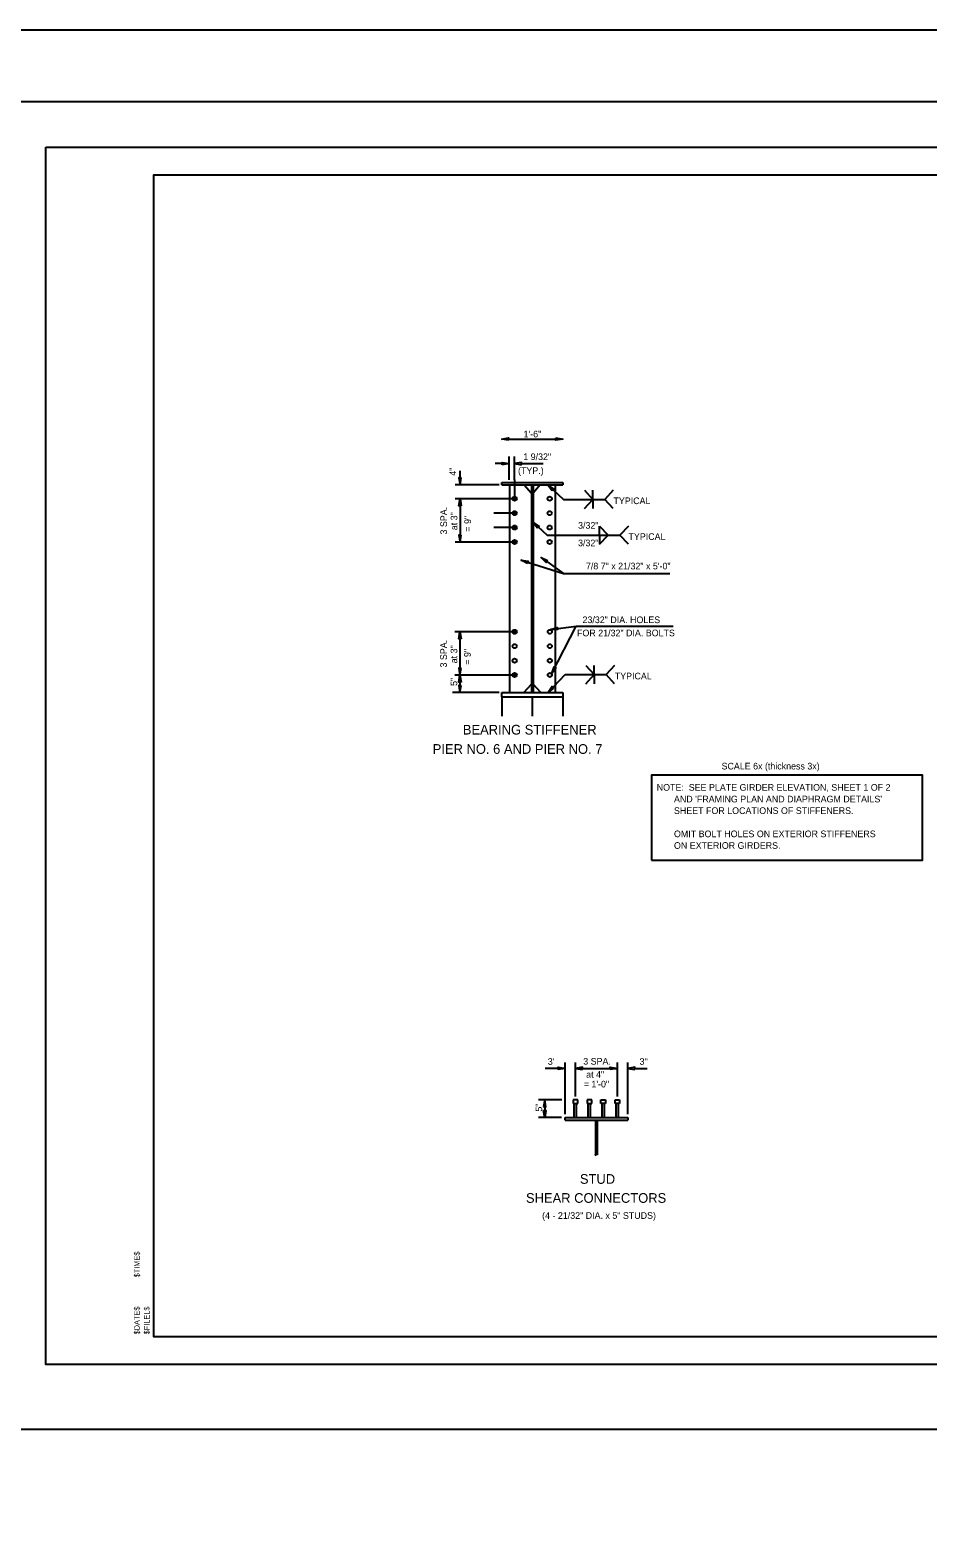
# Model space of a CAD drawing. Extents: x 4944 to 17449, y 3824 to 49087.
# Drawn here: x 8640 to 10198, y 23417 to 26033 of the extents above; entities that cross this region are included whole.
import ezdxf

# ---------------------------------------------------------------- set-up
doc = ezdxf.new("R2010")
doc.units = 0
for name, color, linetype in [('36_S_LINES', 7, 'Continuous'), ('37_S_TXT', 7, 'Continuous'), ('3A', 7, 'Continuous'), ('BEAM', 7, 'Continuous'), ('DIM', 7, 'Continuous'), ('HATCH', 7, 'Continuous'), ('Level 14', 7, 'Continuous'), ('Level 25', 7, 'Continuous'), ('steel', 7, 'Continuous')]:
    doc.layers.add(name, color=color, linetype=linetype)

# ---------------------------------------------------------------- blocks, each defined once
blk = doc.blocks.new('STAMP_')
at = {"layer": 'steel'}
for s, p in [('$TIME$', (8.01, 7.43)), ('$DATE$', (8.01, 2.56)), ('$FILEL$', (8.85, 2.56))]:
    blk.add_text(s, height=0.472, rotation=90, dxfattribs=at).set_placement(p)

msp = doc.modelspace()

# ---------------------------------------------------------------- linework, layer by layer
at = {"layer": '36_S_LINES'}
for p, q in [((9459.4, 25281.2), (9447.2, 25281.2)), ((9471.6, 25252.7), (9471.6, 25293.4)), ((9493.2, 25281.2), (9530.3, 25281.2)), ((9454.3, 25244.2), (9377.6, 25244.2)), ((9386.4, 25256.3), (9386.4, 25268.4)), ((9538.5, 25244.1), (9565.8, 25219)), ((9565.8, 25219), (9637.7, 25219)), ((9602.3, 25234.8), (9617, 25219)), ((9602.3, 25203.2), (9617, 25219)), ((9617, 25218.8), (9617, 25234.8)), ((9617, 25219.2), (9617, 25203.2)), ((9652.3, 25234.8), (9637.7, 25219)), ((9652.3, 25203.2), (9637.7, 25219)), ((9386.4, 25208.1), (9386.4, 25145)), ((9513.1, 25179.4), (9537.5, 25156.9)), ((9628.5, 25156.8), (9628.5, 25172.8)), ((9628.5, 25172.8), (9643.1, 25156.9)), ((9678.4, 25172.8), (9663.8, 25156.9)), ((9537.5, 25156.9), (9663.8, 25156.9)), ((9628.5, 25157.1), (9628.5, 25141.1)), ((9628.5, 25141.1), (9643.1, 25156.9)), ((9678.4, 25141.1), (9663.8, 25156.9)), ((9492.3, 25113.5), (9566.1, 25090.4)), ((9537.1, 25111.1), (9566.1, 25090.4)), ((9566.1, 25090.4), (9750.3, 25090.4)), ((9543.1, 24993), (9587.7, 24999.2)), ((9545.7, 24916.7), (9587.7, 24999.2)), ((9587.7, 24999.2), (9756.4, 24999.2)), ((9386.1, 24977.2), (9386.1, 24914.2)), ((9604.6, 24930.8), (9619.3, 24914.9)), ((9619.3, 24914.8), (9619.3, 24930.8)), ((9654.6, 24930.8), (9640, 24914.9)), ((9539.3, 24884.2), (9568.7, 24914.9)), ((9568.7, 24914.9), (9640, 24914.9)), ((9604.6, 24899.1), (9619.3, 24914.9)), ((9619.3, 24915.1), (9619.3, 24899.1)), ((9654.6, 24899.1), (9640, 24914.9)), ((9454.4, 24884.2), (9373.1, 24884.2)), ((9386.1, 24902.1), (9386.1, 24884.2)), ((9556.4, 24231.8), (9533.9, 24231.8)), ((9568.5, 24152.6), (9568.5, 24241.7)), ((9586.5, 24183.1), (9586.5, 24241.7)), ((9586.5, 24231.8), (9659.3, 24231.8)), ((9659.3, 24183.1), (9659.3, 24241.7)), ((9677.2, 24152.6), (9677.2, 24241.7)), ((9689.4, 24231.8), (9711.3, 24231.8)), ((9563.1, 24177), (9522.7, 24177)), ((9562.5, 24146.6), (9522.7, 24146.6)), ((9533.4, 24164.9), (9533.4, 24146.6)), ((9625.4, 24083.1), (9620.4, 24080.7))]:
    msp.add_line(p, q, dxfattribs=at)
for points in [[(9459.4, 25279.1), (9459.4, 25283.2), (9471.6, 25281.2)], [(9493.2, 25279.1), (9493.2, 25283.2), (9481, 25281.2)], [(9388.4, 25256.3), (9384.3, 25256.3), (9386.4, 25244.2)], [(9546, 25234.3), (9548.8, 25237.3), (9538.5, 25244.1)], [(9388.4, 25208.1), (9384.3, 25208.1), (9386.4, 25220.2)], [(9520.6, 25169.6), (9523.4, 25172.6), (9513.1, 25179.4)], [(9388.4, 25157.2), (9384.3, 25157.2), (9386.4, 25145)], [(9503.1, 25108), (9492.3, 25113.5), (9504.3, 25111.8)], [(9538.3, 25112.8), (9535.9, 25109.5), (9527.2, 25118.2)], [(9388.2, 24977.2), (9384.1, 24977.2), (9386.1, 24989.3)], [(9555.3, 24992.6), (9543.1, 24993), (9554.7, 24996.6)], [(9388.2, 24926.3), (9384.1, 24926.3), (9386.1, 24914.2)], [(9388.2, 24902.1), (9384.1, 24902.1), (9386.1, 24914.2)], [(9552.9, 24926.5), (9545.7, 24916.7), (9549.4, 24928.3)], [(9388.2, 24896.3), (9384.1, 24896.3), (9386.1, 24884.2)], [(9549.2, 24891.5), (9546.3, 24894.3), (9539.3, 24884.2)], [(9556.4, 24229.8), (9556.4, 24233.9), (9568.5, 24231.8)], [(9598.6, 24229.8), (9598.6, 24233.9), (9586.5, 24231.8)], [(9647.1, 24229.8), (9647.1, 24233.9), (9659.3, 24231.8)], [(9689.4, 24229.8), (9689.4, 24233.9), (9677.2, 24231.8)], [(9531.3, 24164.9), (9535.4, 24164.9), (9533.4, 24177)], [(9531.3, 24158.7), (9535.4, 24158.7), (9533.4, 24146.6)]]:
    msp.add_lwpolyline(points, close=True, dxfattribs=at)
at = {"layer": '37_S_TXT'}
msp.add_lwpolyline([(8510.3, 25909.4), (11966.3, 25909.4), (11966.3, 23605.3), (8510.3, 23605.3)], close=True, dxfattribs=at)
at = {"layer": '3A'}
for p, q in [((9481, 25252.7), (9481, 25293.4)), ((9458.8, 25220.2), (9377.6, 25220.2)), ((9458.8, 25145), (9377.6, 25145)), ((9458.6, 24989.3), (9377.4, 24989.3)), ((9458.6, 24914.2), (9377.4, 24914.2))]:
    msp.add_line(p, q, dxfattribs=at)
msp.add_lwpolyline([(9718.3, 24593), (10188.7, 24593), (10188.7, 24740.6), (9718.3, 24740.6)], close=True, dxfattribs=at)
at = {"layer": 'DEFPOINTS'}
for p, q in [((9470.6, 25323.7), (9552.6, 25323.7)), ((9481, 25252.7), (9481, 25219.1)), ((9484, 25220.2), (9445, 25220.2)), ((9484, 25195.1), (9445, 25195.1)), ((9484, 25170.1), (9445, 25170.1)), ((9484, 25145), (9445, 25145)), ((9483.8, 24989.3), (9444.8, 24989.3)), ((9483.8, 24914.2), (9444.8, 24914.2)), ((9458.6, 24875.6), (9458.6, 24842.6)), ((9511.6, 24875.6), (9511.6, 24842.6)), ((9564.6, 24875.6), (9564.6, 24842.6))]:
    msp.add_line(p, q, dxfattribs=at)
for points in [[(9470.6, 25321.7), (9458.6, 25323.7), (9470.6, 25325.7)], [(9552.6, 25325.7), (9564.6, 25323.7), (9552.6, 25321.7)]]:
    msp.add_lwpolyline(points, close=True, dxfattribs=at)
at = {"layer": 'DIM'}
msp.add_lwpolyline([(8667.5, 25830.2), (11931.5, 25830.2), (11931.5, 23718.1), (8667.5, 23718.1)], close=True, dxfattribs=at)
at = {"layer": 'HATCH'}
msp.add_lwpolyline([(5400.2, 12194.1), (15037.9, 12194.1), (15037.9, 26033.1), (5400.2, 26033.1)], close=True, dxfattribs=at)
at = {"layer": 'Level 14'}
msp.add_lwpolyline([(11878.7, 23766.1), (8854.7, 23766.1), (8854.7, 25782.2), (11878.7, 25782.2)], close=True, dxfattribs=at)
at = {"layer": 'Level 25'}
for p, q in [((9458.6, 25248.2), (9564.6, 25248.2)), ((9458.6, 25244.2), (9458.6, 25248.2)), ((9458.6, 25244.2), (9564.6, 25244.2)), ((9472, 25244.2), (9472, 24884.2)), ((9497.6, 25244.2), (9510, 25229.8)), ((9510, 25244.2), (9510, 24884.2)), ((9513.1, 25244.2), (9513.1, 24884.2)), ((9525.5, 25244.2), (9513.1, 25229.8)), ((9551.1, 25244.2), (9551.1, 24884.2)), ((9564.6, 25248.2), (9564.6, 25244.2)), ((9458.6, 24884.2), (9564.6, 24884.2)), ((9458.6, 24876.7), (9458.6, 24884.2)), ((9496.9, 24884.2), (9510, 24898.3)), ((9526.3, 24884.2), (9513.1, 24898.3)), ((9564.6, 24884.2), (9564.6, 24876.7)), ((9458.6, 24876.7), (9564.6, 24876.7)), ((9590.5, 24177), (9582.5, 24177)), ((9582.5, 24177), (9582.5, 24171.1)), ((9590.5, 24171.1), (9590.5, 24177)), ((9606.9, 24177), (9606.9, 24171.1)), ((9614.8, 24177), (9606.9, 24177)), ((9614.8, 24171.1), (9614.8, 24177)), ((9630.9, 24177), (9638.9, 24177)), ((9630.9, 24171.1), (9630.9, 24177)), ((9638.9, 24177), (9638.9, 24171.1)), ((9655.3, 24171.1), (9655.3, 24177)), ((9655.3, 24177), (9663.2, 24177)), ((9663.2, 24177), (9663.2, 24171.1)), ((9568.5, 24146.6), (9677.2, 24146.6)), ((9568.5, 24141.7), (9568.5, 24146.6)), ((9582.5, 24171.1), (9590.5, 24171.1)), ((9584.5, 24146.6), (9584.5, 24171.1)), ((9588.5, 24146.6), (9588.5, 24171.1)), ((9606.9, 24171.1), (9614.8, 24171.1)), ((9608.8, 24146.6), (9608.8, 24171.1)), ((9612.9, 24146.6), (9612.9, 24171.1)), ((9638.9, 24171.1), (9630.9, 24171.1)), ((9632.9, 24146.6), (9632.9, 24171.1)), ((9636.9, 24146.6), (9636.9, 24171.1)), ((9663.2, 24171.1), (9655.3, 24171.1)), ((9657.3, 24146.6), (9657.3, 24171.1)), ((9661.3, 24146.6), (9661.3, 24171.1)), ((9677.2, 24146.6), (9677.2, 24141.7)), ((9568.5, 24141.7), (9677.2, 24141.7)), ((9621.4, 24141.7), (9621.4, 24081.1)), ((9624.4, 24141.7), (9624.4, 24082.6)), ((9624.4, 24083), (9624.4, 24141.7))]:
    msp.add_line(p, q, dxfattribs=at)
for centre, radius in [((9481, 25220.2), 3.67), ((9541.9, 25220.2), 3.67), ((9481, 25195.1), 3.62), ((9541.9, 25195.1), 3.62), ((9481, 25170.1), 3.62), ((9541.9, 25170.1), 3.62), ((9481, 25145), 3.62), ((9541.9, 25145), 3.62), ((9481, 24989.3), 3.62), ((9542.1, 24989.3), 3.62), ((9481, 24964.3), 3.62), ((9542.1, 24964.3), 3.62), ((9481, 24939.2), 3.62), ((9542.1, 24939.2), 3.62), ((9481, 24914.2), 3.62), ((9542.1, 24914.2), 3.62)]:
    msp.add_circle(centre, radius, dxfattribs=at)

# ---------------------------------------------------------------- block references
at = {"layer": 'steel', "xscale": 20.32004064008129, "yscale": 20.32004064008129}
msp.add_blockref('STAMP_', (8667.5, 23718.1), dxfattribs=at)

# ---------------------------------------------------------------- texts
at = {"layer": '3A'}
for s, p in [('1 9/32"', (9496, 25287.2)), ('(TYP.)', (9486.9, 25263.2)), ('TYPICAL', (9652.5, 25210.8)), ('3/32"', (9591.1, 25168.1)), ('3/32"', (9591.1, 25137.7)), ('TYPICAL', (9678.6, 25148.7)), ('7/8 7" x 21/32" x 5\'-0"', (9604.7, 25097.5)), ('23/32" DIA. HOLES', (9598.8, 25004.3)), ('FOR 21/32" DIA. BOLTS', (9589.3, 24981.5)), ('TYPICAL', (9654.8, 24906.7)), ('NOTE:  SEE PLATE GIRDER ELEVATION, SHEET 1 OF 2 ', (9727.6, 24713.5)), ("       AND 'FRAMING PLAN AND DIAPHRAGM DETAILS' ", (9727.6, 24693.3)), ('       SHEET FOR LOCATIONS OF STIFFENERS. ', (9727.6, 24673.2)), ('       OMIT BOLT HOLES ON EXTERIOR STIFFENERS ', (9727.6, 24632.9)), ('       ON EXTERIOR GIRDERS.', (9727.6, 24612.7)), ('3 SPA.', (9600.1, 24238.3)), ("3'", (9538.6, 24237.9)), ('at 4"', (9605.2, 24215.5)), ('3"', (9697.9, 24237.9)), ('= 1\'-0"', (9601, 24198.7)), ('(4 - 21/32" DIA. x 5" STUDS)', (9528.7, 23970.7))]:
    msp.add_text(s, height=11.52, dxfattribs=at).set_placement(p)
for s, p in [('4"', (9379.4, 25260.1)), ('3 SPA.', (9363.6, 25158.1)), ('at 3"', (9381.6, 25165.5)), ('= 9"', (9405.2, 25163.1)), ('3 SPA.', (9363.4, 24927.3)), ('at 3"', (9381.4, 24934.6)), ('= 9"', (9404.9, 24932.2)), ('5"', (9381.4, 24895.4)), ('5"', (9528.8, 24156.8))]:
    msp.add_text(s, height=11.52, rotation=90, dxfattribs=at).set_placement(p)
at = {"layer": 'BEAM'}
for s, p in [('BEARING STIFFENER', (9391.1, 24811)), ('PIER NO. 6 AND PIER NO. 7', (9338.8, 24777.5)), ('STUD', (9594.3, 24031.5)), ('SHEAR CONNECTORS', (9500.7, 23998.5))]:
    msp.add_text(s, height=16.8, dxfattribs=at).set_placement(p)
at = {"layer": 'DEFPOINTS'}
for s, p in [('1\'-6"', (9496.5, 25326.5)), ('SCALE 6x (thickness 3x)', (9840.1, 24750.4))]:
    msp.add_text(s, height=11.52, dxfattribs=at).set_placement(p)

doc.saveas('drawing.dxf')
